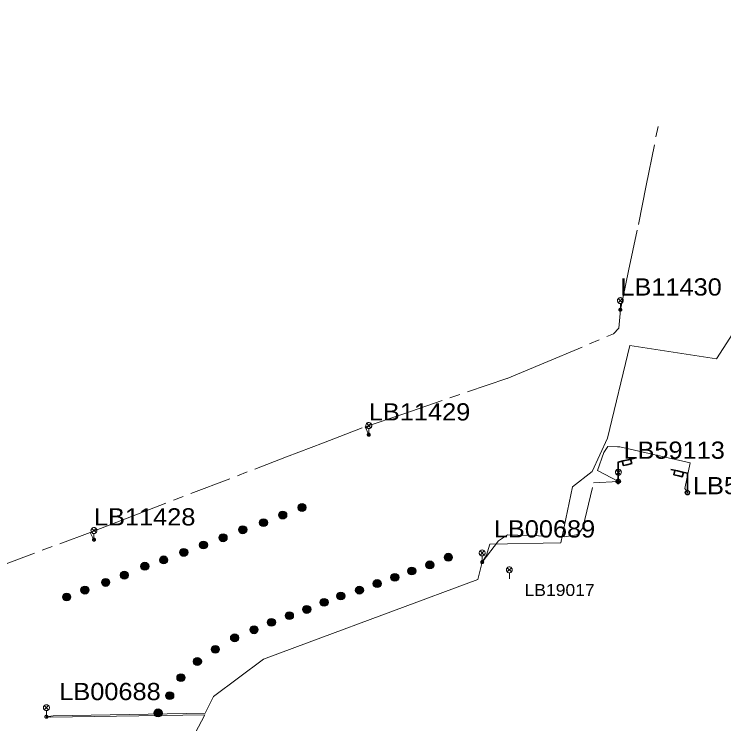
# Model space of a CAD drawing. Extents: x -688049 to -687261, y -973611 to -973038.
# Drawn here: x -687682.8 to -687593.4, y -973324.5 to -973235.2 of the extents above; entities that cross this region are included whole.
import ezdxf

# ---------------------------------------------------------------- set-up
doc = ezdxf.new("R2010")
doc.units = 0
doc.header["$LTSCALE"] = 0.87
doc.linetypes.add('LONG_DASH_SHORT_DASH', pattern=[9.9, 6, -1.2, 1.5, -1.2])
doc.layers.add('1', color=7, linetype='Continuous', lineweight=13)

msp = doc.modelspace()

# ---------------------------------------------------------------- hatches: boundary and pattern name
at = {"layer": '1'}
for points in [[(-687646.387, -973297.741, 1), (-687646.686, -973296.797, 1)], [(-687648.817, -973298.693, 1), (-687649.116, -973297.748, 1)], [(-687651.24, -973299.653, 1), (-687651.538, -973298.708, 1)], [(-687653.848, -973300.542, 1), (-687654.146, -973299.598, 1)], [(-687656.327, -973301.549, 1), (-687656.626, -973300.605, 1)], [(-687658.792, -973302.463, 1), (-687659.091, -973301.519, 1)], [(-687661.271, -973303.392, 1), (-687661.57, -973302.448, 1)], [(-687663.806, -973304.334, 1), (-687664.105, -973303.39, 1)], [(-687627.969, -973304.001, 1), (-687628.268, -973303.057, 1)], [(-687666.175, -973305.136, 1), (-687666.473, -973304.191, 1)], [(-687630.297, -973304.965, 1), (-687630.595, -973304.021, 1)], [(-687668.75, -973306.257, 1), (-687669.049, -973305.313, 1)], [(-687632.569, -973305.736, 1), (-687632.868, -973304.791, 1)], [(-687671.105, -973307.172, 1), (-687671.404, -973306.227, 1)], [(-687634.704, -973306.534, 1), (-687635.003, -973305.59, 1)], [(-687636.931, -973307.313, 1), (-687637.23, -973306.369, 1)], [(-687673.718, -973308.138, 1), (-687674.017, -973307.193, 1)], [(-687641.505, -973308.876, 1), (-687641.804, -973307.932, 1)], [(-687639.159, -973308.149, 1), (-687639.458, -973307.205, 1)], [(-687676.014, -973309.003, 1), (-687676.312, -973308.059, 1)], [(-687643.612, -973309.674, 1), (-687643.911, -973308.73, 1)], [(-687645.788, -973310.569, 1), (-687646.087, -973309.625, 1)], [(-687647.978, -973311.354, 1), (-687648.277, -973310.41, 1)], [(-687650.241, -973312.194, 1), (-687650.54, -973311.25, 1)], [(-687652.427, -973313.13, 1), (-687652.726, -973312.185, 1)], [(-687654.873, -973314.142, 1), (-687655.172, -973313.198, 1)], [(-687657.298, -973315.595, 1), (-687657.597, -973314.651, 1)], [(-687659.551, -973317.124, 1), (-687659.85, -973316.18, 1)], [(-687661.627, -973319.151, 1), (-687661.926, -973318.206, 1)], [(-687663.042, -973321.417, 1), (-687663.341, -973320.473, 1)], [(-687664.502, -973323.592, 1), (-687664.801, -973322.647, 1)]]:
    msp.add_hatch(color=256, dxfattribs=at).paths.add_polyline_path(points)

# ---------------------------------------------------------------- linework, layer by layer
for p, q in [((-687606.735, -973270.975), (-687606.205, -973271.505)), ((-687606.735, -973271.505), (-687606.205, -973270.975)), ((-687606.47, -973272.39), (-687606.47, -973271.615)), ((-687638.395, -973286.695), (-687637.865, -973287.225)), ((-687638.395, -973287.225), (-687637.865, -973286.695)), ((-687638.13, -973288.11), (-687638.13, -973287.335)), ((-687606.98, -973292.569), (-687606.45, -973293.099)), ((-687606.98, -973293.099), (-687606.45, -973292.569)), ((-687606.715, -973293.984), (-687606.715, -973293.209)), ((-687672.99, -973299.905), (-687672.46, -973300.435)), ((-687672.99, -973300.435), (-687672.46, -973299.905)), ((-687672.725, -973301.32), (-687672.725, -973300.545)), ((-687624.125, -973302.725), (-687623.595, -973303.255)), ((-687624.125, -973303.255), (-687623.595, -973302.725)), ((-687623.86, -973304.14), (-687623.86, -973303.365)), ((-687620.706, -973304.85), (-687620.176, -973305.38)), ((-687620.706, -973305.38), (-687620.176, -973304.85)), ((-687620.441, -973306.265), (-687620.441, -973305.49)), ((-687678.975, -973322.195), (-687678.445, -973322.725)), ((-687678.975, -973322.725), (-687678.445, -973322.195)), ((-687678.71, -973323.61), (-687678.71, -973322.835))]:
    msp.add_line(p, q, dxfattribs=at)
at = {"layer": '1', "linetype": 'LONG_DASH_SHORT_DASH'}
for p, q in [((-687638.58, -973287.12), (-687633.848, -973285.506)), ((-687673.22, -973300.4), (-687668.553, -973298.606))]:
    msp.add_line(p, q, dxfattribs=at)
at = {"layer": '1', "lineweight": 35}
for p, q in [((-687606.769, -973293.984), (-687606.715, -973293.984)), ((-687597.993, -973295.4), (-687598.047, -973295.4))]:
    msp.add_line(p, q, dxfattribs=at)
at = {"layer": '1'}
for points in [[(-687581.366, -973235.196), (-687581.366, -973248.239), (-687582.584, -973268.559), (-687591.459, -973274.079), (-687594.36, -973278.544), (-687605.262, -973276.884), (-687608.072, -973288.54), (-687610.025, -973292.76), (-687612.471, -973294.66), (-687613.949, -973301.72), (-687622.891, -973301.881), (-687623.316, -973303.267), (-687623.86, -973304.14)], [(-687606.82, -973289.62), (-687606.547, -973289.625), (-687597.664, -973291.631), (-687598.336, -973294.87), (-687598.016, -973295.4)], [(-687623.86, -973304.14), (-687624.41, -973306.316), (-687645.619, -973314.208), (-687651.378, -973316.368), (-687657.664, -973321.036), (-687658.709, -973323.167), (-687677.869, -973323.466), (-687678.71, -973323.61)], [(-687678.71, -973323.61), (-687678.206, -973323.669), (-687658.771, -973323.345), (-687661.643, -973328.751), (-687661.643, -973334.873), (-687659.29, -973340.758), (-687653.159, -973347.738), (-687635.491, -973365.599), (-687635.62, -973366.14)]]:
    msp.add_lwpolyline(points, dxfattribs=at)
at = {"layer": '1', "linetype": 'LONG_DASH_SHORT_DASH'}
for points in [[(-687605.435, -973267.498), (-687604.2, -973261.66), (-687603.216, -973256.758), (-687601.65, -973248.95)], [(-687616.108, -973279.098), (-687607.33, -973275.42), (-687606.66, -973274.72), (-687606.47, -973272.39), (-687605.435, -973267.498)], [(-687633.848, -973285.506), (-687620.72, -973281.03), (-687616.108, -973279.098)], [(-687643.828, -973289.12), (-687638.58, -973287.12), (-687638.13, -973288.11)], [(-687668.553, -973298.606), (-687648.5, -973290.9), (-687643.828, -973289.12)], [(-687623.86, -973304.14), (-687621.8, -973301.48), (-687620.67, -973300.69), (-687613.46, -973300.95), (-687611.76, -973300.67), (-687611.19, -973299.82), (-687609.856, -973294.173), (-687606.715, -973293.984), (-687609.324, -973292.607), (-687608.56, -973290.36), (-687608.03, -973289.6), (-687606.82, -973289.62)], [(-687685.096, -973304.839), (-687673.22, -973300.4), (-687672.75, -973301.32)]]:
    msp.add_lwpolyline(points, dxfattribs=at)
at = {"layer": '1'}
for points in [[(-687606.095, -973271.24), (-687606.101, -973271.175), (-687606.118, -973271.112), (-687606.145, -973271.052), (-687606.183, -973270.999), (-687606.229, -973270.953), (-687606.282, -973270.915), (-687606.342, -973270.888), (-687606.405, -973270.871), (-687606.47, -973270.865), (-687606.535, -973270.871), (-687606.598, -973270.888), (-687606.658, -973270.915), (-687606.711, -973270.953), (-687606.757, -973270.999), (-687606.795, -973271.052), (-687606.822, -973271.112), (-687606.839, -973271.175), (-687606.845, -973271.24), (-687606.839, -973271.305), (-687606.822, -973271.368), (-687606.795, -973271.428), (-687606.757, -973271.481), (-687606.711, -973271.527), (-687606.658, -973271.565), (-687606.598, -973271.592), (-687606.535, -973271.609), (-687606.47, -973271.615), (-687606.405, -973271.609), (-687606.342, -973271.592), (-687606.282, -973271.565), (-687606.229, -973271.527), (-687606.183, -973271.481), (-687606.145, -973271.428), (-687606.118, -973271.368), (-687606.101, -973271.305)], [(-687606.28, -973272.39), (-687606.283, -973272.357), (-687606.291, -973272.325), (-687606.305, -973272.295), (-687606.324, -973272.268), (-687606.348, -973272.244), (-687606.375, -973272.225), (-687606.405, -973272.211), (-687606.437, -973272.203), (-687606.47, -973272.2), (-687606.503, -973272.203), (-687606.535, -973272.211), (-687606.565, -973272.225), (-687606.592, -973272.244), (-687606.616, -973272.268), (-687606.635, -973272.295), (-687606.649, -973272.325), (-687606.657, -973272.357), (-687606.66, -973272.39), (-687606.657, -973272.423), (-687606.649, -973272.455), (-687606.635, -973272.485), (-687606.616, -973272.512), (-687606.592, -973272.536), (-687606.565, -973272.555), (-687606.535, -973272.569), (-687606.503, -973272.577), (-687606.47, -973272.58), (-687606.437, -973272.577), (-687606.405, -973272.569), (-687606.375, -973272.555), (-687606.348, -973272.536), (-687606.324, -973272.512), (-687606.305, -973272.485), (-687606.291, -973272.455), (-687606.283, -973272.423)], [(-687606.42, -973272.39), (-687606.421, -973272.381), (-687606.423, -973272.373), (-687606.427, -973272.365), (-687606.432, -973272.358), (-687606.438, -973272.352), (-687606.445, -973272.347), (-687606.453, -973272.343), (-687606.461, -973272.341), (-687606.47, -973272.34), (-687606.479, -973272.341), (-687606.487, -973272.343), (-687606.495, -973272.347), (-687606.502, -973272.352), (-687606.508, -973272.358), (-687606.513, -973272.365), (-687606.517, -973272.373), (-687606.519, -973272.381), (-687606.52, -973272.39), (-687606.519, -973272.399), (-687606.517, -973272.407), (-687606.513, -973272.415), (-687606.508, -973272.422), (-687606.502, -973272.428), (-687606.495, -973272.433), (-687606.487, -973272.437), (-687606.479, -973272.439), (-687606.47, -973272.44), (-687606.461, -973272.439), (-687606.453, -973272.437), (-687606.445, -973272.433), (-687606.438, -973272.428), (-687606.432, -973272.422), (-687606.427, -973272.415), (-687606.423, -973272.407), (-687606.421, -973272.399)], [(-687637.755, -973286.96), (-687637.761, -973286.895), (-687637.778, -973286.832), (-687637.805, -973286.772), (-687637.843, -973286.719), (-687637.889, -973286.673), (-687637.942, -973286.635), (-687638.002, -973286.608), (-687638.065, -973286.591), (-687638.13, -973286.585), (-687638.195, -973286.591), (-687638.258, -973286.608), (-687638.318, -973286.635), (-687638.371, -973286.673), (-687638.417, -973286.719), (-687638.455, -973286.772), (-687638.482, -973286.832), (-687638.499, -973286.895), (-687638.505, -973286.96), (-687638.499, -973287.025), (-687638.482, -973287.088), (-687638.455, -973287.148), (-687638.417, -973287.201), (-687638.371, -973287.247), (-687638.318, -973287.285), (-687638.258, -973287.312), (-687638.195, -973287.329), (-687638.13, -973287.335), (-687638.065, -973287.329), (-687638.002, -973287.312), (-687637.942, -973287.285), (-687637.889, -973287.247), (-687637.843, -973287.201), (-687637.805, -973287.148), (-687637.778, -973287.088), (-687637.761, -973287.025)], [(-687637.94, -973288.11), (-687637.943, -973288.077), (-687637.951, -973288.045), (-687637.965, -973288.015), (-687637.984, -973287.988), (-687638.008, -973287.964), (-687638.035, -973287.945), (-687638.065, -973287.931), (-687638.097, -973287.923), (-687638.13, -973287.92), (-687638.163, -973287.923), (-687638.195, -973287.931), (-687638.225, -973287.945), (-687638.252, -973287.964), (-687638.276, -973287.988), (-687638.295, -973288.015), (-687638.309, -973288.045), (-687638.317, -973288.077), (-687638.32, -973288.11), (-687638.317, -973288.143), (-687638.309, -973288.175), (-687638.295, -973288.205), (-687638.276, -973288.232), (-687638.252, -973288.256), (-687638.225, -973288.275), (-687638.195, -973288.289), (-687638.163, -973288.297), (-687638.13, -973288.3), (-687638.097, -973288.297), (-687638.065, -973288.289), (-687638.035, -973288.275), (-687638.008, -973288.256), (-687637.984, -973288.232), (-687637.965, -973288.205), (-687637.951, -973288.175), (-687637.943, -973288.143)], [(-687638.08, -973288.11), (-687638.081, -973288.101), (-687638.083, -973288.093), (-687638.087, -973288.085), (-687638.092, -973288.078), (-687638.098, -973288.072), (-687638.105, -973288.067), (-687638.113, -973288.063), (-687638.121, -973288.061), (-687638.13, -973288.06), (-687638.139, -973288.061), (-687638.147, -973288.063), (-687638.155, -973288.067), (-687638.162, -973288.072), (-687638.168, -973288.078), (-687638.173, -973288.085), (-687638.177, -973288.093), (-687638.179, -973288.101), (-687638.18, -973288.11), (-687638.179, -973288.119), (-687638.177, -973288.127), (-687638.173, -973288.135), (-687638.168, -973288.142), (-687638.162, -973288.148), (-687638.155, -973288.153), (-687638.147, -973288.157), (-687638.139, -973288.159), (-687638.13, -973288.16), (-687638.121, -973288.159), (-687638.113, -973288.157), (-687638.105, -973288.153), (-687638.098, -973288.148), (-687638.092, -973288.142), (-687638.087, -973288.135), (-687638.083, -973288.127), (-687638.081, -973288.119)], [(-687606.34, -973292.834), (-687606.346, -973292.769), (-687606.363, -973292.706), (-687606.39, -973292.646), (-687606.428, -973292.593), (-687606.474, -973292.547), (-687606.528, -973292.509), (-687606.587, -973292.482), (-687606.65, -973292.465), (-687606.715, -973292.459), (-687606.78, -973292.465), (-687606.843, -973292.482), (-687606.902, -973292.509), (-687606.956, -973292.547), (-687607.002, -973292.593), (-687607.04, -973292.646), (-687607.067, -973292.706), (-687607.084, -973292.769), (-687607.09, -973292.834), (-687607.084, -973292.899), (-687607.067, -973292.962), (-687607.04, -973293.022), (-687607.002, -973293.075), (-687606.956, -973293.121), (-687606.902, -973293.159), (-687606.843, -973293.186), (-687606.78, -973293.203), (-687606.715, -973293.209), (-687606.65, -973293.203), (-687606.587, -973293.186), (-687606.528, -973293.159), (-687606.474, -973293.121), (-687606.428, -973293.075), (-687606.39, -973293.022), (-687606.363, -973292.962), (-687606.346, -973292.899)], [(-687606.525, -973293.984), (-687606.528, -973293.951), (-687606.536, -973293.919), (-687606.55, -973293.889), (-687606.569, -973293.862), (-687606.593, -973293.838), (-687606.62, -973293.819), (-687606.65, -973293.805), (-687606.682, -973293.797), (-687606.715, -973293.794), (-687606.748, -973293.797), (-687606.78, -973293.805), (-687606.81, -973293.819), (-687606.837, -973293.838), (-687606.861, -973293.862), (-687606.88, -973293.889), (-687606.894, -973293.919), (-687606.902, -973293.951), (-687606.905, -973293.984), (-687606.902, -973294.017), (-687606.894, -973294.049), (-687606.88, -973294.079), (-687606.861, -973294.106), (-687606.837, -973294.13), (-687606.81, -973294.149), (-687606.78, -973294.163), (-687606.748, -973294.171), (-687606.715, -973294.174), (-687606.682, -973294.171), (-687606.65, -973294.163), (-687606.62, -973294.149), (-687606.593, -973294.13), (-687606.569, -973294.106), (-687606.55, -973294.079), (-687606.536, -973294.049), (-687606.528, -973294.017)], [(-687606.665, -973293.984), (-687606.666, -973293.975), (-687606.668, -973293.967), (-687606.672, -973293.959), (-687606.677, -973293.952), (-687606.683, -973293.946), (-687606.69, -973293.941), (-687606.698, -973293.937), (-687606.706, -973293.935), (-687606.715, -973293.934), (-687606.724, -973293.935), (-687606.732, -973293.937), (-687606.74, -973293.941), (-687606.747, -973293.946), (-687606.753, -973293.952), (-687606.758, -973293.959), (-687606.762, -973293.967), (-687606.764, -973293.975), (-687606.765, -973293.984), (-687606.764, -973293.993), (-687606.762, -973294.001), (-687606.758, -973294.009), (-687606.753, -973294.016), (-687606.747, -973294.022), (-687606.74, -973294.027), (-687606.732, -973294.031), (-687606.724, -973294.033), (-687606.715, -973294.034), (-687606.706, -973294.033), (-687606.698, -973294.031), (-687606.69, -973294.027), (-687606.683, -973294.022), (-687606.677, -973294.016), (-687606.672, -973294.009), (-687606.668, -973294.001), (-687606.666, -973293.993)], [(-687672.35, -973300.17), (-687672.356, -973300.105), (-687672.373, -973300.042), (-687672.4, -973299.982), (-687672.438, -973299.929), (-687672.484, -973299.883), (-687672.538, -973299.845), (-687672.597, -973299.818), (-687672.66, -973299.801), (-687672.725, -973299.795), (-687672.79, -973299.801), (-687672.853, -973299.818), (-687672.912, -973299.845), (-687672.966, -973299.883), (-687673.012, -973299.929), (-687673.05, -973299.982), (-687673.077, -973300.042), (-687673.094, -973300.105), (-687673.1, -973300.17), (-687673.094, -973300.235), (-687673.077, -973300.298), (-687673.05, -973300.357), (-687673.012, -973300.411), (-687672.966, -973300.457), (-687672.912, -973300.495), (-687672.853, -973300.522), (-687672.79, -973300.539), (-687672.725, -973300.545), (-687672.66, -973300.539), (-687672.597, -973300.522), (-687672.538, -973300.495), (-687672.484, -973300.457), (-687672.438, -973300.411), (-687672.4, -973300.357), (-687672.373, -973300.298), (-687672.356, -973300.235)], [(-687672.535, -973301.32), (-687672.538, -973301.287), (-687672.546, -973301.255), (-687672.56, -973301.225), (-687672.579, -973301.198), (-687672.603, -973301.174), (-687672.63, -973301.155), (-687672.66, -973301.141), (-687672.692, -973301.133), (-687672.725, -973301.13), (-687672.758, -973301.133), (-687672.79, -973301.141), (-687672.82, -973301.155), (-687672.847, -973301.174), (-687672.871, -973301.198), (-687672.89, -973301.225), (-687672.904, -973301.255), (-687672.912, -973301.287), (-687672.915, -973301.32), (-687672.912, -973301.353), (-687672.904, -973301.385), (-687672.89, -973301.415), (-687672.871, -973301.442), (-687672.847, -973301.466), (-687672.82, -973301.485), (-687672.79, -973301.499), (-687672.758, -973301.507), (-687672.725, -973301.51), (-687672.692, -973301.507), (-687672.66, -973301.499), (-687672.63, -973301.485), (-687672.603, -973301.466), (-687672.579, -973301.442), (-687672.56, -973301.415), (-687672.546, -973301.385), (-687672.538, -973301.353)], [(-687672.675, -973301.32), (-687672.676, -973301.311), (-687672.678, -973301.303), (-687672.682, -973301.295), (-687672.687, -973301.288), (-687672.693, -973301.282), (-687672.7, -973301.277), (-687672.708, -973301.273), (-687672.716, -973301.271), (-687672.725, -973301.27), (-687672.734, -973301.271), (-687672.742, -973301.273), (-687672.75, -973301.277), (-687672.757, -973301.282), (-687672.763, -973301.288), (-687672.768, -973301.295), (-687672.772, -973301.303), (-687672.774, -973301.311), (-687672.775, -973301.32), (-687672.774, -973301.329), (-687672.772, -973301.337), (-687672.768, -973301.345), (-687672.763, -973301.352), (-687672.757, -973301.358), (-687672.75, -973301.363), (-687672.742, -973301.367), (-687672.734, -973301.369), (-687672.725, -973301.37), (-687672.716, -973301.369), (-687672.708, -973301.367), (-687672.7, -973301.363), (-687672.693, -973301.358), (-687672.687, -973301.352), (-687672.682, -973301.345), (-687672.678, -973301.337), (-687672.676, -973301.329)], [(-687623.485, -973302.99), (-687623.491, -973302.925), (-687623.508, -973302.862), (-687623.535, -973302.802), (-687623.573, -973302.749), (-687623.619, -973302.703), (-687623.672, -973302.665), (-687623.732, -973302.638), (-687623.795, -973302.621), (-687623.86, -973302.615), (-687623.925, -973302.621), (-687623.988, -973302.638), (-687624.048, -973302.665), (-687624.101, -973302.703), (-687624.147, -973302.749), (-687624.185, -973302.802), (-687624.212, -973302.862), (-687624.229, -973302.925), (-687624.235, -973302.99), (-687624.229, -973303.055), (-687624.212, -973303.118), (-687624.185, -973303.178), (-687624.147, -973303.231), (-687624.101, -973303.277), (-687624.048, -973303.315), (-687623.988, -973303.342), (-687623.925, -973303.359), (-687623.86, -973303.365), (-687623.795, -973303.359), (-687623.732, -973303.342), (-687623.672, -973303.315), (-687623.619, -973303.277), (-687623.573, -973303.231), (-687623.535, -973303.178), (-687623.508, -973303.118), (-687623.491, -973303.055)], [(-687623.67, -973304.14), (-687623.673, -973304.107), (-687623.681, -973304.075), (-687623.695, -973304.045), (-687623.714, -973304.018), (-687623.738, -973303.994), (-687623.765, -973303.975), (-687623.795, -973303.961), (-687623.827, -973303.953), (-687623.86, -973303.95), (-687623.893, -973303.953), (-687623.925, -973303.961), (-687623.955, -973303.975), (-687623.982, -973303.994), (-687624.006, -973304.018), (-687624.025, -973304.045), (-687624.039, -973304.075), (-687624.047, -973304.107), (-687624.05, -973304.14), (-687624.047, -973304.173), (-687624.039, -973304.205), (-687624.025, -973304.235), (-687624.006, -973304.262), (-687623.982, -973304.286), (-687623.955, -973304.305), (-687623.925, -973304.319), (-687623.893, -973304.327), (-687623.86, -973304.33), (-687623.827, -973304.327), (-687623.795, -973304.319), (-687623.765, -973304.305), (-687623.738, -973304.286), (-687623.714, -973304.262), (-687623.695, -973304.235), (-687623.681, -973304.205), (-687623.673, -973304.173)], [(-687623.81, -973304.14), (-687623.811, -973304.131), (-687623.813, -973304.123), (-687623.817, -973304.115), (-687623.822, -973304.108), (-687623.828, -973304.102), (-687623.835, -973304.097), (-687623.843, -973304.093), (-687623.851, -973304.091), (-687623.86, -973304.09), (-687623.869, -973304.091), (-687623.877, -973304.093), (-687623.885, -973304.097), (-687623.892, -973304.102), (-687623.898, -973304.108), (-687623.903, -973304.115), (-687623.907, -973304.123), (-687623.909, -973304.131), (-687623.91, -973304.14), (-687623.909, -973304.149), (-687623.907, -973304.157), (-687623.903, -973304.165), (-687623.898, -973304.172), (-687623.892, -973304.178), (-687623.885, -973304.183), (-687623.877, -973304.187), (-687623.869, -973304.189), (-687623.86, -973304.19), (-687623.851, -973304.189), (-687623.843, -973304.187), (-687623.835, -973304.183), (-687623.828, -973304.178), (-687623.822, -973304.172), (-687623.817, -973304.165), (-687623.813, -973304.157), (-687623.811, -973304.149)], [(-687620.066, -973305.115), (-687620.072, -973305.05), (-687620.089, -973304.987), (-687620.116, -973304.928), (-687620.154, -973304.874), (-687620.2, -973304.828), (-687620.254, -973304.79), (-687620.313, -973304.763), (-687620.376, -973304.746), (-687620.441, -973304.74), (-687620.506, -973304.746), (-687620.569, -973304.763), (-687620.628, -973304.79), (-687620.682, -973304.828), (-687620.728, -973304.874), (-687620.766, -973304.928), (-687620.793, -973304.987), (-687620.81, -973305.05), (-687620.816, -973305.115), (-687620.81, -973305.18), (-687620.793, -973305.243), (-687620.766, -973305.302), (-687620.728, -973305.356), (-687620.682, -973305.402), (-687620.628, -973305.44), (-687620.569, -973305.467), (-687620.506, -973305.484), (-687620.441, -973305.49), (-687620.376, -973305.484), (-687620.313, -973305.467), (-687620.254, -973305.44), (-687620.2, -973305.402), (-687620.154, -973305.356), (-687620.116, -973305.302), (-687620.089, -973305.243), (-687620.072, -973305.18)], [(-687678.335, -973322.46), (-687678.341, -973322.395), (-687678.358, -973322.332), (-687678.385, -973322.272), (-687678.423, -973322.219), (-687678.469, -973322.173), (-687678.522, -973322.135), (-687678.582, -973322.108), (-687678.645, -973322.091), (-687678.71, -973322.085), (-687678.775, -973322.091), (-687678.838, -973322.108), (-687678.898, -973322.135), (-687678.951, -973322.173), (-687678.997, -973322.219), (-687679.035, -973322.272), (-687679.062, -973322.332), (-687679.079, -973322.395), (-687679.085, -973322.46), (-687679.079, -973322.525), (-687679.062, -973322.588), (-687679.035, -973322.648), (-687678.997, -973322.701), (-687678.951, -973322.747), (-687678.898, -973322.785), (-687678.838, -973322.812), (-687678.775, -973322.829), (-687678.71, -973322.835), (-687678.645, -973322.829), (-687678.582, -973322.812), (-687678.522, -973322.785), (-687678.469, -973322.747), (-687678.423, -973322.701), (-687678.385, -973322.648), (-687678.358, -973322.588), (-687678.341, -973322.525)], [(-687678.52, -973323.61), (-687678.523, -973323.577), (-687678.531, -973323.545), (-687678.545, -973323.515), (-687678.564, -973323.488), (-687678.588, -973323.464), (-687678.615, -973323.445), (-687678.645, -973323.431), (-687678.677, -973323.423), (-687678.71, -973323.42), (-687678.743, -973323.423), (-687678.775, -973323.431), (-687678.805, -973323.445), (-687678.832, -973323.464), (-687678.856, -973323.488), (-687678.875, -973323.515), (-687678.889, -973323.545), (-687678.897, -973323.577), (-687678.9, -973323.61), (-687678.897, -973323.643), (-687678.889, -973323.675), (-687678.875, -973323.705), (-687678.856, -973323.732), (-687678.832, -973323.756), (-687678.805, -973323.775), (-687678.775, -973323.789), (-687678.743, -973323.797), (-687678.71, -973323.8), (-687678.677, -973323.797), (-687678.645, -973323.789), (-687678.615, -973323.775), (-687678.588, -973323.756), (-687678.564, -973323.732), (-687678.545, -973323.705), (-687678.531, -973323.675), (-687678.523, -973323.643)], [(-687678.66, -973323.61), (-687678.661, -973323.601), (-687678.663, -973323.593), (-687678.667, -973323.585), (-687678.672, -973323.578), (-687678.678, -973323.572), (-687678.685, -973323.567), (-687678.693, -973323.563), (-687678.701, -973323.561), (-687678.71, -973323.56), (-687678.719, -973323.561), (-687678.727, -973323.563), (-687678.735, -973323.567), (-687678.742, -973323.572), (-687678.748, -973323.578), (-687678.753, -973323.585), (-687678.757, -973323.593), (-687678.759, -973323.601), (-687678.76, -973323.61), (-687678.759, -973323.619), (-687678.757, -973323.627), (-687678.753, -973323.635), (-687678.748, -973323.642), (-687678.742, -973323.648), (-687678.735, -973323.653), (-687678.727, -973323.657), (-687678.719, -973323.659), (-687678.71, -973323.66), (-687678.701, -973323.659), (-687678.693, -973323.657), (-687678.685, -973323.653), (-687678.678, -973323.648), (-687678.672, -973323.642), (-687678.667, -973323.635), (-687678.663, -973323.627), (-687678.661, -973323.619)]]:
    msp.add_lwpolyline(points, close=True, dxfattribs=at)
at = {"layer": '1', "lineweight": 35}
for points in [[(-687606.742, -973293.729), (-687606.655, -973293.729), (-687606.52, -973293.827), (-687606.466, -973293.984), (-687606.52, -973294.141), (-687606.655, -973294.239), (-687606.823, -973294.239), (-687606.959, -973294.141), (-687607.013, -973293.984), (-687606.959, -973293.827), (-687606.823, -973293.729), (-687606.742, -973293.729), (-687606.742, -973293.041), (-687606.742, -973292.353), (-687606.742, -973291.665), (-687606.742, -973291.546), (-687606.108, -973291.399), (-687605.474, -973291.253), (-687604.84, -973291.107), (-687604.629, -973291.058)], [(-687605.171, -973291.193), (-687605.035, -973291.735), (-687605.669, -973291.882), (-687606.092, -973291.979), (-687606.227, -973291.437)], [(-687598.02, -973295.145), (-687598.107, -973295.145), (-687598.242, -973295.243), (-687598.296, -973295.4), (-687598.242, -973295.557), (-687598.107, -973295.655), (-687597.939, -973295.655), (-687597.803, -973295.557), (-687597.749, -973295.4), (-687597.803, -973295.243), (-687597.939, -973295.145), (-687598.02, -973295.145), (-687598.02, -973294.457), (-687598.02, -973293.769), (-687598.02, -973293.081), (-687598.02, -973292.962), (-687598.654, -973292.815), (-687599.288, -973292.669), (-687599.922, -973292.523), (-687600.133, -973292.474)], [(-687599.591, -973292.609), (-687599.727, -973293.151), (-687599.093, -973293.298), (-687598.67, -973293.395), (-687598.535, -973292.853)]]:
    msp.add_lwpolyline(points, dxfattribs=at)
at = {"layer": '1', "lineweight": 25}
for centre in [(-687646.537, -973297.269), (-687648.967, -973298.221), (-687651.389, -973299.181), (-687653.997, -973300.07), (-687656.476, -973301.077), (-687658.942, -973301.991), (-687661.421, -973302.92), (-687663.955, -973303.862), (-687628.119, -973303.529), (-687666.324, -973304.664), (-687630.446, -973304.493), (-687668.9, -973305.785), (-687632.719, -973305.264), (-687671.255, -973306.699), (-687634.853, -973306.062), (-687637.081, -973306.841), (-687673.867, -973307.666), (-687641.654, -973308.404), (-687639.308, -973307.677), (-687676.163, -973308.531), (-687643.762, -973309.202), (-687645.938, -973310.097), (-687648.128, -973310.882), (-687650.39, -973311.722), (-687652.577, -973312.657), (-687655.022, -973313.67), (-687657.448, -973315.123), (-687659.701, -973316.652), (-687661.777, -973318.679), (-687663.191, -973320.945), (-687664.651, -973323.12)]:
    msp.add_circle(centre, 0.495, dxfattribs=at)

# ---------------------------------------------------------------- texts
at = {"layer": '1', "width": 1.1}
for s, height, p in [('LB11430', 2.168, (-687606.47, -973270.602)), ('LB11429', 2.168, (-687638.13, -973286.322)), ('LB59113', 2.167, (-687606.077, -973291.14)), ('LB59114', 2.167, (-687597.328, -973295.603)), ('LB11428', 2.168, (-687672.725, -973299.532)), ('LB00689', 2.167, (-687622.395, -973301.045)), ('LB19017', 1.5, (-687618.532, -973308.405)), ('LB00688', 2.167, (-687677.088, -973321.51))]:
    msp.add_text(s, height=height, dxfattribs=at).set_placement(p)

doc.saveas('drawing.dxf')
